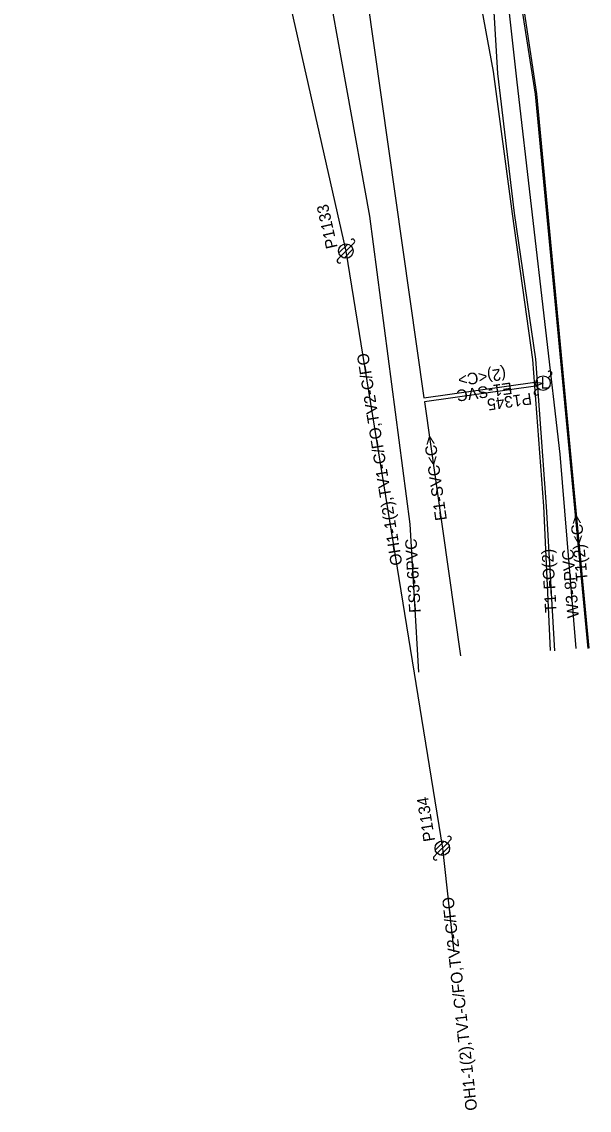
# Model space of a CAD drawing. Extents: x 2336688 to 2352634, y 362473 to 369571.
# Drawn here: x 2346765.4 to 2346960.9, y 366541.2 to 366916.1 of the extents above; entities that cross this region are included whole.
import ezdxf

# ---------------------------------------------------------------- set-up
doc = ezdxf.new("R2010")
doc.units = 0
for name, color, linetype in [('RD_EX_DV_Prop', 7, 'Continuous'), ('RD_EX_DV_TX_Prop', 7, 'Continuous'), ('RD_EX_RW', 7, 'Continuous'), ('RD_EX_RW_TX', 7, 'Continuous'), ('RD_HC_Data_Tic', 7, 'Continuous'), ('RD_PD_CstnLmt', 7, 'Continuous'), ('RD_PD_Final_TrvlWay', 7, 'Continuous'), ('RD_PD_PatLn4', 7, 'Continuous'), ('RD_SHT_ShtClip', 7, 'Continuous'), ('RD_Sketch1', 7, 'Continuous'), ('RD_Sketch2', 7, 'Continuous'), ('RD_Sketch5', 7, 'Continuous')]:
    doc.layers.add(name, color=color, linetype=linetype)

msp = doc.modelspace()

# ---------------------------------------------------------------- linework, layer by layer
at = {"layer": 'RD_EX_RW_TX'}
for points in [[(2346960.84, 366700.32), (2346942.78, 366891.31), (2346933.69, 366952.5), (2346898, 367161.71), (2346898.36, 367165.45)], [(2346897.18, 367161.87), (2346932.76, 366952.15), (2346942.29, 366891.15), (2346960.4, 366700.28)], [(2346918.58, 366948.75), (2346927.75, 366898.93), (2346934.33, 366849.92), (2346941.31, 366799.82), (2346945.16, 366749.26), (2346947.38, 366699.52)], [(2346949.01, 366699.45), (2346946.14, 366749.2), (2346942.44, 366799.91), (2346935.08, 366850.14), (2346929.43, 366898.3), (2346926.24, 366950.27)]]:
    msp.add_lwpolyline(points, dxfattribs=at)
at = {"layer": 'RD_HC_Data_Tic'}
for p, q in [((2346874.64, 366836.47), (2346877.71, 366839.53)), ((2346875.29, 366835.35), (2346878.83, 366838.88)), ((2346878.83, 366838.88), (2346879.89, 366839.94)), ((2346874.23, 366834.29), (2346875.29, 366835.35)), ((2346876.41, 366834.7), (2346879.47, 366837.76)), ((2346946.73, 366793.42), (2346947.79, 366794.48)), ((2346942.13, 366788.82), (2346943.2, 366789.89)), ((2346907.86, 366630.84), (2346910.93, 366633.9)), ((2346908.51, 366629.72), (2346912.05, 366633.25)), ((2346912.05, 366633.25), (2346913.11, 366634.31)), ((2346907.45, 366628.65), (2346908.51, 366629.72)), ((2346909.63, 366629.07), (2346912.69, 366632.13))]:
    msp.add_line(p, q, dxfattribs=at)
for centre in [(2346877.06, 366837.12), (2346944.96, 366791.65), (2346910.28, 366631.48)]:
    msp.add_circle(centre, 2.5, dxfattribs=at)
for centre, start, end in [((2346879.36, 366840.47), 315, 135), ((2346874.76, 366833.76), 135, 315), ((2346947.26, 366795.01), 315, 135), ((2346942.66, 366788.29), 135, 315), ((2346912.58, 366634.84), 315, 135), ((2346907.98, 366628.12), 135, 315)]:
    msp.add_arc(centre, 0.75, start, end, dxfattribs=at)
at = {"layer": 'RD_PD_Final_TrvlWay'}
msp.add_lwpolyline([(2346809.48, 367136.35), (2346814.29, 367128.92), (2346821.6, 367129.86), (2346874.93, 366991.01), (2346881.39, 366945.36), (2346881.77, 366943.7), (2346881.86, 366942.04), (2346903.9, 366786.54), (2346942.12, 366791.96), (2346944.96, 366791.65), (2346942.32, 366790.57), (2346904.1, 366785.15), (2346916.49, 366697.73)], dxfattribs=at)
at = {"layer": 'RD_SHT_ShtClip'}
for p, q in [((2346809.48, 367136.35), (2346877.06, 366837.12)), ((2346877.06, 366837.12), (2346910.28, 366631.48)), ((2346910.28, 366631.48), (2346914.26, 366595.74))]:
    msp.add_line(p, q, dxfattribs=at)
at = {"layer": 'RD_Sketch2'}
msp.add_lwpolyline([(2346907.18, 367191.36), (2346873.77, 367179.55), (2346874.94, 367172.89), (2346883.31, 367148.26), (2346906.9, 367059.09), (2346929.73, 366951.1), (2346935.93, 366895.33), (2346950.72, 366767.23), (2346956.21, 366700.28)], dxfattribs=at)
at = {"layer": 'RD_Sketch5'}
msp.add_lwpolyline([(2346765.39, 367271.81), (2346776.02, 367241.77), (2346794.17, 367204.89), (2346798.54, 367192.2), (2346810.66, 367155.29), (2346821.32, 367118.37), (2346834.62, 367075.46), (2346843.34, 367041.99), (2346854.83, 366998.67), (2346869.3, 366936.93), (2346885.2, 366849.09), (2346899.13, 366743.03), (2346902.03, 366692.09)], dxfattribs=at)

# ---------------------------------------------------------------- texts
at = {"layer": 'RD_EX_DV_Prop'}
for s, rotation, p in [('(2)<C>', 188.0663, (2346931.95, 366796.88)), ('E1-SVC', 188.0663, (2346934.03, 366791.92)), ('E1-SVC<C>', 98.0663, (2346911.87, 366744.57))]:
    msp.add_text(s, height=4, rotation=rotation, dxfattribs=at).set_placement(p)
at = {"layer": 'RD_EX_DV_TX_Prop'}
for s, rotation, p in [('P1133', 102.726, (2346874.22, 366838.44)), ('P1345', 188.0663, (2346940.79, 366788.31)), ('P1134', 99.1766, (2346907.82, 366634.09))]:
    msp.add_text(s, height=4, rotation=rotation, dxfattribs=at).set_placement(p)
at = {"layer": 'RD_EX_RW'}
for s, rotation, p in [('T1(2)<C>', 95.4019, (2346960.39, 366723.62)), ('T1-FO(2)', 93.3022, (2346949.68, 366712.71))]:
    msp.add_text(s, height=4, rotation=rotation, dxfattribs=at).set_placement(p)
at = {"layer": 'RD_HC_Data_Tic'}
msp.add_text('L', height=4, rotation=360, dxfattribs=at).set_placement((2346944.15, 366789.72))
at = {"layer": 'RD_PD_CstnLmt'}
msp.add_text('W3-8PVC', height=4, rotation=94.6909, dxfattribs=at).set_placement((2346957.35, 366710.89))
at = {"layer": 'RD_PD_PatLn4'}
for rotation, p in [(99.1766, (2346896.53, 366729.16)), (96.3495, (2346922.32, 366541.31))]:
    msp.add_text('OH1-1(2),TV1-C/FO,TV2-C/FO', height=4, rotation=rotation, dxfattribs=at).set_placement(p)
at = {"layer": 'RD_Sketch1'}
msp.add_text('FS3-6PVC', height=4, rotation=93.2578, dxfattribs=at).set_placement((2346902.86, 366712.67))

doc.saveas('drawing.dxf')
